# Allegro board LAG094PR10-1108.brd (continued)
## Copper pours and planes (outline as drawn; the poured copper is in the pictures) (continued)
LG_VNN on BOTTOM (solid shape): 85.8,131.33 85.8,130.46 85.85,130.41 85.85,128.94 85.77,128.86 85.44,128.86 85.37,128.94 85.37,129.92 85.57,130.12 85.57,130.44 85.59,130.46 85.59,131.33 85.64,131.38 85.75,131.38
LG_VNN on IN2 (solid shape): 84.64,123.55 84.64,122.98 84.77,122.86 84.77,122.41 84.64,122.28 83.85,122.28 83.7,122.44 83.7,122.79 83.88,122.97 83.88,123.58 84.62,123.58
LG_VNN on IN2 (solid shape): 85.82,129.82 85.82,128.36 85.44,127.98 84.99,127.98 84.74,128.23 84.74,128.68 84.93,128.87 84.93,129.82 85.05,129.95 85.69,129.95
LX_1.2V on TOP (solid shape): 24.23,115.92 24.23,115.16 23.85,114.78 23.82,114.8 23.4,114.74 23.34,114.32 23.36,114.29 23.28,114.21 23.28,114.17 23.21,114.1 23.21,113.71 23.21,113.71 23.21,113.41 23.15,113.34 22.56,113.34 22.46,113.44 22.46,114.98 22.48,114.99 22.6,115.08 22.66,115.21 22.67,115.23 22.91,115.46 23.54,115.46 23.58,115.5 23.6,115.5 24.08,115.97 24.18,115.97
LX_1.2V on BOTTOM (solid shape): 23.34,104.77 26.01,104.77 26.13,104.64 26.13,103.69 26.07,103.63 22.26,103.63 21.94,103.31 20.42,103.31 19.85,102.74 17.88,102.74 17.31,103.31 17.31,105.98 17.5,106.17 21.94,106.17
LX_1.2V on IN2 (solid shape): 23.66,104.9 23.66,103.82 23.47,103.63 23.08,103.63 22.83,103.88 22.83,104.96 22.89,105.02 23.53,105.02
LX_1.2V on IN2 (solid shape): 23.66,115.25 23.66,114.99 23.28,114.61 23.28,114.23 23.08,114.04 22.58,114.04 22.51,114.1 22.51,114.99 22.89,115.37 23.53,115.37
LX_1.05V on TOP (solid shape): 144.23,63.34 144.23,60.87 144.2,60.84 143.24,60.84 143.04,61.04 143.04,63.29 143.24,63.5 144.08,63.5
LX_1.05V on BOTTOM (solid shape): 149.2,63.81 149.2,61.91 149.07,61.78 147.84,61.78 147.4,62.21 145.96,62.21 145.5,61.76 145.5,60.08 145.27,59.85 142.9,59.85 142.87,59.86 142.82,59.87 142.77,59.88 142.72,59.87 142.67,59.86 142.64,59.85 142.27,59.85 142.23,59.86 142.18,59.87 142.13,59.88 142.08,59.87 142.03,59.86 141.99,59.85 141.94,59.9 141.94,62.92 142.3,63.28 144.25,63.28 144.25,63.23 144.26,63.18 144.27,63.13 144.29,63.08 144.32,63.03 144.36,63 144.4,62.96 144.45,62.94 144.5,62.92 144.55,62.9 144.6,62.9 144.66,62.9 144.71,62.92 144.76,62.94 144.8,62.96 144.85,63 144.88,63.03 144.91,63.08 144.94,63.13 144.95,63.18 144.96,63.23 144.96,63.28 144.95,63.34 144.94,63.39 144.91,63.44 144.88,63.48 144.85,63.52 144.8,63.55 144.76,63.58 144.71,63.6 144.66,63.61 144.6,63.61 144.55,63.61 144.5,63.6 144.45,63.58 144.4,63.55 144.36,63.52 144.32,63.48 144.29,63.44 144.27,63.39 144.26,63.34 144.25,63.28 142.3,63.28 143.02,64 149.01,64
LX_1.8V on TOP (solid shape): 51.66,34.16 51.66,33.08 51.22,32.63 49.31,32.63 49.18,32.76 49.18,33.65 49.31,33.78 49.37,33.78 49.88,34.29 51.53,34.29
LX_1.8V on BOTTOM (solid shape): 52.1,33.84 52.1,31.11 51.98,30.98 49.63,30.98 48.23,32.38 47.34,32.38 47.28,32.44 47.28,33.08 47.34,33.14 48.17,33.14 48.87,33.84 49.63,33.84 49.75,33.97 51.98,33.97
LX_1.24V on TOP (solid shape): 65.92,43.52 65.92,37.81 65.69,37.59 62.96,37.59 62.9,37.65 62.9,38.67 62.96,38.73 64.55,38.73 64.87,39.05 64.87,42.41 64.61,42.67 63.79,42.67 63.72,42.73 63.72,43.37 63.79,43.43 64.68,43.43 64.93,43.68 65.76,43.68
LX_1.24V on BOTTOM (solid shape): 67.03,43.24 67.03,37.78 66.01,36.76 63.41,36.76 63.22,36.95 63.22,39.37 64.68,40.83 64.68,43.24 64.93,43.49 66.77,43.49
LX_3V on TOP (solid shape): 165.4,60.57 165.48,60.53 165.5,60.44 165.83,59.96 166.17,60.44 166.18,60.53 166.26,60.57 170.21,60.57 170.4,60.38 170.4,59.62 170.28,59.5 166.54,59.5 165.64,59.49 165.26,59.11 163.48,59.11 163.36,59.24 163.36,60.45 163.48,60.57
LX_3V on BOTTOM (solid shape): 170.4,59.94 170.4,59.43 170.09,59.11 168.94,59.11 168.88,59.18 168.88,59.37 169.52,60 170.34,60
LX_3V on BOTTOM (solid shape): 164.75,61.65 164.88,61.53 164.88,61.08 165.07,60.89 166.09,60.89 166.53,60.45 166.53,59.49 166.72,59.3 166.72,58.73 166.66,58.67 165.77,58.67 165.64,58.8 165.5,58.8 165.02,58.8 165.02,58.8 164.5,58.8 164.37,58.67 159.55,58.67 159.42,58.8 159.42,60.35 165.48,60.35 165.48,60.29 165.48,60.24 165.5,60.19 165.52,60.14 165.55,60.1 165.59,60.06 165.63,60.03 165.68,60 165.73,59.98 165.78,59.97 165.83,59.96 165.89,59.97 165.94,59.98 165.99,60 166.03,60.03 166.08,60.06 166.11,60.1 166.14,60.14 166.16,60.19 166.18,60.24 166.19,60.29 166.19,60.35 166.18,60.4 166.16,60.45 166.14,60.5 166.11,60.54 166.08,60.58 166.03,60.62 165.99,60.64 165.94,60.66 165.89,60.67 165.83,60.68 165.78,60.67 165.73,60.66 165.68,60.64 165.63,60.62 165.59,60.58 165.55,60.54 165.52,60.5 165.5,60.45 165.48,60.4 165.48,60.35 159.42,60.35 159.42,61.34 159.74,61.65 164.19,61.65
LX_5V on TOP (solid shape): outline of 97 points within 202.98,77.08 210.28,78.48
LX_5V on BOTTOM (solid shape): 204.38,78.74 204.38,78.61 204.25,78.48 204.25,78.04 204.12,77.91 203.86,77.91 203.62,78.01 203.37,77.91 203.04,77.91 202.98,77.97 202.98,78.74 203.04,78.8 204.31,78.8
LX_5V on BOTTOM (solid shape): 212,81.02 212,76.64 211.68,76.32 207.43,76.32 207.36,76.39 207.36,77.21 206.92,77.66 206.92,77.81 206.96,77.81 207.27,78.19 206.9,78.52 206.88,78.52 206.85,78.54 206.66,78.54 206.6,78.61 206.6,79.18 206.66,79.24 207.43,79.24 207.55,79.12 208.89,79.12 209.2,79.43 209.2,80.96 209.39,81.15 211.87,81.15
LX_CHG on TOP (solid shape): 182.96,51.06 182.96,49.28 182.89,49.21 181.97,49.21 181.87,49.31 181.87,49.87 181.8,49.94 181.14,49.94 181.06,50.02 181.06,51.04 181.14,51.11 182.91,51.11
LX_CHG on BOTTOM (solid shape): 193.65,48.89 193.65,48.83 193.58,48.76 192.88,48.76 192.31,48.19 192.31,47.81 191.55,47.05 190.6,47.05 190.41,47.24 190.41,47.87 190.57,48.04 191.68,48.04 191.99,48.35 192.04,48.37 192.09,48.39 192.14,48.39 192.7,48.95 193.58,48.95
LX_CHG on BOTTOM (solid shape): 183.1,51.68 183.1,49.97 183.49,49.59 184.12,49.59 184.37,49.33 184.37,46.48 184.18,46.29 179.17,46.29 178.72,46.73 178.72,49.59 181.16,49.59 181.16,49.54 181.17,49.48 181.19,49.43 181.21,49.39 181.24,49.34 181.27,49.3 181.32,49.27 181.36,49.24 181.41,49.22 181.46,49.21 181.52,49.21 181.57,49.21 181.62,49.22 181.67,49.24 181.72,49.27 181.76,49.3 181.8,49.34 181.83,49.39 181.85,49.43 181.86,49.48 181.87,49.54 181.87,49.59 181.86,49.64 181.85,49.69 181.83,49.74 181.8,49.79 181.76,49.82 181.72,49.86 181.67,49.88 181.62,49.9 181.57,49.92 181.52,49.92 181.46,49.92 181.41,49.9 181.36,49.88 181.32,49.86 181.27,49.82 181.24,49.79 181.21,49.74 181.19,49.69 181.17,49.64 181.16,49.59 178.72,49.59 178.72,51.49 179.04,51.81 182.98,51.81
LX_CHG on IN2 (solid shape): 192.29,48.22 192.29,47.68 192.01,47.4 190.92,47.4 190.76,47.56 190.76,48.27 190.84,48.34 192.16,48.34
LX_CHG on IN2 (solid shape): 183.55,49.75 183.55,49.16 183.41,49.02 181.98,49.02 181.87,49.13 181.87,49.75 181.97,49.85 183.45,49.85
LX_VCCGI on TOP (solid shape): 93.38,118.65 93.38,116.87 93.28,116.77 93.04,116.77 92.79,116.87 92.55,116.77 90.43,116.77 90.36,116.85 90.36,118.63 90.51,118.78 93.25,118.78
LX_VCCGI on BOTTOM (solid shape): 97.57,135.64 97.57,134.76 97.6,134.73 97.6,134.25 97.95,133.89 97.95,132.19 97.9,132.14 97.39,132.14 97.34,132.19 97.34,135.64 97.39,135.69 97.52,135.69
LX_VCCGI on BOTTOM (solid shape): outline of 96 points within 91.28,111.25 102.21,122.11
LX_VCCGI on IN2 (solid shape): 97.63,117.85 97.63,116.68 97.38,116.42 96.62,116.42 96.6,116.44 96.38,116.44 96.24,116.58 96.24,117.66 96.55,117.98 97.51,117.98
LX_VCCGI on IN2 (solid shape): 98.52,133.86 98.52,132.01 98.08,131.57 97.82,131.57 97.44,131.95 97.44,133.92 97.57,134.05 98.33,134.05
LX_VNN on TOP (solid shape): 85.75,119.38 85.83,119.33 85.84,119.23 86.08,118.74 86.52,119.07 86.59,119.16 86.69,119.14 86.78,119.06 86.78,116.87 86.62,116.71 85.63,116.71 85.51,116.84 85.51,117.66 84.62,118.55 84.62,119.18 84.81,119.38
LX_VNN on BOTTOM (solid shape): 86.2,131.33 86.2,130.44 86.23,130.41 86.23,129.93 86.58,129.57 86.58,127.87 86.53,127.82 86.03,127.82 85.97,127.87 85.97,131.33 86.03,131.38 86.15,131.38
LX_VNN on BOTTOM (solid shape): 85.94,122.08 85.94,119.44 85.78,119.29 85.78,118.8 85.89,118.7 86.91,118.7 87.63,117.98 87.63,116.49 87.38,116.23 85.98,116.23 85.98,117.18 85.09,117.18 85.09,116.23 83.76,116.23 83.76,119.03 84.17,119.44 84.67,119.44 84.81,119.58 84.81,122.17 84.9,122.26 85.75,122.26
LX_VNN on IN2 (solid shape): 86.8,129.31 86.8,127.74 86.67,127.61 86.2,127.61 86.04,127.77 86.04,129.58 86.17,129.71 86.41,129.71
LX_VNN on IN2 (solid shape): 85.89,120.01 85.89,119.3 85.81,119.13 85.84,118.93 85.86,118.9 85.76,118.8 84.87,118.8 84.74,118.93 84.74,119.69 85.12,120.07 85.82,120.07
Net_23 on TOP (solid shape): 218.97,70.29 210.97,70.29 210.97,78.29 218.97,78.29
Net_24 on TOP (solid shape): 60.61,103.44 52.61,103.44 52.61,111.44 60.61,111.44
QPCN_CHG on BOTTOM (solid shape): 194.79,48.13 194.79,46.86 193.77,45.84 193.77,44.83 193.71,44.76 192.63,44.76 192.57,44.83 192.57,45.78 192.82,46.03 193.39,46.03 194.6,47.24 194.6,48.13 194.66,48.19 194.73,48.19
QPCP_CHG on BOTTOM (solid shape): 195.61,48.13 195.61,46.99 195.93,46.67 195.93,45.91 195.74,45.72 194.85,45.72 194.6,45.46 194.6,44.76 194.55,44.72 194.02,44.72 193.96,44.78 193.96,45.72 194.34,46.1 195.11,46.1 195.42,46.41 195.42,48.13 195.49,48.19 195.55,48.19
REGOUT on TOP (solid shape): 17.9,87.24 18.32,87.24 18.39,87.18 18.39,86.55 18.45,86.48 19.21,86.48 19.47,86.74 20.61,86.74 20.93,86.42 20.93,85.66 20.86,85.59 18.07,85.59 17.94,85.72 17.94,86.36 17.37,86.92 17.37,87.32 17.52,87.47 17.68,87.47
REGOUT on BOTTOM (solid shape): 21.56,87.82 21.56,87.18 21.43,87.05 20.74,87.05 19.27,85.59 18.07,85.59 17.88,85.78 17.88,87.31 18.54,87.97 21.4,87.97
RING2 on TOP (solid shape): 33.03,17.1 33.03,16.34 32.77,16.09 32.77,15.17 32.72,15.12 32.6,15.12 32.55,15.17 32.55,17.13 32.62,17.2 32.93,17.2
RING2 on TOP (solid shape): 21.31,15.36 21.94,15.36 22.01,15.3 22.01,14.54 21.88,14.41 20.16,14.41 20.04,14.54 20.04,15.24 20.16,15.36 20.74,15.36 20.87,15.5 21.17,15.5
RING2 on BOTTOM (solid shape): 22.45,14.92 21.88,14.35 20.93,14.35 20.74,14.54 20.74,15.3 20.93,15.49 21.69,15.49 21.94,15.74 22.45,15.74
RING2 on BOTTOM (solid shape): 33.12,18.22 33.12,16.25 32.99,16.12 32.67,16.12 32.55,16.25 32.55,17.2 32.36,17.39 32.23,17.39 32.23,18.41 32.93,18.41
RING2_R on TOP (solid shape): 23.75,17.74 23.75,16.83 23.28,16.35 23.28,14.79 23.08,14.6 22.32,14.6 22.32,17.14 21.88,17.58 21.18,17.58 20.93,17.84 20.93,18.98 21.12,19.17 22.32,19.17
RING2_R on IN1 (solid shape): 21.5,18.79 21.5,17.9 20.54,16.95 20.16,16.95 19.91,17.2 19.91,17.71 20.48,18.28 20.48,18.79 20.67,18.98 21.31,18.98
RING2_R on IN1 (solid shape): 5.72,8.26 5.72,7.63 5.67,7.58 5.75,7.58 5.75,6.99 5.57,6.82 4.2,6.82 3.97,7.04 3.97,8.26 4.1,8.39 5.6,8.39
RTC_PWR on TOP (solid shape): 112.68,59.24 112.68,58.86 112.43,58.61 112.43,56.57 112.37,56.51 111.86,56.51 111.6,56.76 111.29,56.76 110.97,56.45 109.55,56.45 109.33,56.67 109.33,57.33 109.68,57.69 110.16,57.69 111.12,58.65 111.12,59.43 111.25,59.56 112.37,59.56
SLEEVE on TOP (solid shape): 18.77,15.11 18.77,13.33 18.36,12.92 17.73,12.92 17.62,13.03 17.62,15.04 17.75,15.17 18.7,15.17
SLEEVE on IN1 (solid shape): 19.15,14.98 19.15,13.97 19.08,13.9 17.75,13.9 17.62,14.03 17.62,14.92 17.75,15.04 19.08,15.04
SLEEVE on IN1 (solid shape): 32.42,17.58 32.42,16.31 32.29,16.19 31.78,16.19 31.66,16.31 31.66,16.76 31.4,17.01 31.21,17.01 31.21,18.03 31.97,18.03
SLEEVE_R on TOP (solid shape): 20.61,18.98 20.61,17.78 19.91,17.08 19.91,14.73 19.78,14.6 19.08,14.6 18.96,14.73 18.96,18.98 19.15,19.17 20.42,19.17
SLEEVE_R on IN1 (solid shape): 5.57,18.07 5.57,17.08 5.39,16.9 3.36,16.9 3.26,17 3.26,18.07 3.34,18.14 5.27,18.14 5.29,18.17 5.47,18.17
SLEEVE_R on IN1 (solid shape): 19.66,18.85 19.66,17.9 18.64,16.89 18.26,16.89 17.94,17.2 17.94,17.65 18.7,18.41 18.7,18.79 18.89,18.98 19.53,18.98
SN_1.2V on TOP (solid shape): 22.96,102.8 22.96,102.17 22.89,102.1 20.93,102.1 20.74,102.29 20.74,103.94 20.8,104.01 21.75,104.01
SN_1.05V on TOP (solid shape): 147.99,62.54 147.99,61.34 147.86,61.21 147.23,61.21 146.91,60.89 145.89,60.89 145.83,60.96 145.83,62.61 145.89,62.67 147.86,62.67
SN_1.8V on TOP (solid shape): 51.79,31.3 52.55,31.3 52.55,30.73 52.36,30.54 49.88,30.54 49.88,31.55 51.53,31.55
SN_1.24V on TOP (solid shape): 64.61,41.33 64.61,39.87 64.3,39.56 62.01,39.56 61.95,39.62 61.95,40.13 62.01,40.19 62.77,40.19 62.96,40.38 62.96,41.33 63.03,41.4 64.55,41.4
SN_3V on TOP (solid shape): 166.66,57.53 166.66,56.7 166.59,56.64 165.45,56.64 165.26,56.45 163.42,56.45 163.36,56.51 163.36,57.59 163.42,57.65 166.53,57.65
SN_5V on TOP (solid shape): 210.22,81.08 210.22,80.01 210.09,79.88 207.55,79.88 207.49,79.94 207.49,80.7 207.55,80.77 208.06,80.77 208.44,81.15 210.16,81.15
SN_CHG on TOP (solid shape): 183.82,48.28 183.82,47.39 183.75,47.33 181.15,47.33 181.15,48.34 183.75,48.34
SN_VCCGI on TOP (solid shape): 92.12,121.54 92.12,119.52 92.02,119.43 90.45,119.43 90.37,119.5 90.37,120.75 91.3,121.67 91.98,121.67
SN_VNN on TOP (solid shape): 84.11,119.25 84.11,116.84 83.98,116.71 82.97,116.71 82.84,116.84 82.84,119.25 82.97,119.38 83.98,119.38
UG_1.2V on TOP (solid shape): 24.63,115.95 24.63,114.05 24.45,113.87 23.96,113.87 23.84,113.98 23.84,114.18 24,114.39 23.97,114.65 24.41,115.08 24.41,115.95 24.46,116 24.58,116
UG_1.2V on BOTTOM (solid shape): 24.16,106.61 24.16,105.85 24.04,105.72 23.47,105.72 23.34,105.6 23.08,105.6 22.96,105.72 22.96,106.61 23.08,106.74 24.04,106.74
UG_1.2V on IN2 (solid shape): 24.99,114.93 24.99,113.98 24.93,113.91 24.16,113.91 24.04,114.04 24.04,114.8 24.23,114.99 24.93,114.99
UG_1.2V on IN2 (solid shape): 24.55,107.88 24.55,105.91 24.23,105.6 23.08,105.6 22.96,105.72 22.96,106.61 23.85,107.5 23.85,107.82 24.04,108.01 24.42,108.01
UG_CHG on BOTTOM (solid shape): 193.66,49.31 193.66,49.21 193.61,49.16 192.72,49.16 192.08,48.52 191.75,48.52 191.7,48.57 191.7,48.85 192.21,49.36 193.61,49.36
UG_CHG on BOTTOM (solid shape): 183.1,52.7 183.1,52.13 182.98,52 180.88,52 180.76,52.13 180.76,52.76 180.82,52.83 182.98,52.83
UG_CHG on IN2 (solid shape): 182.51,52.56 182.51,52.15 182.2,51.85 180.88,51.85 180.81,51.93 180.81,52.48 180.93,52.61 182.46,52.61
UG_CHG on IN2 (solid shape): 192.22,49.82 192.29,49.8 192.37,49.81 192.54,49.64 192.54,48.8 192.21,48.47 191.5,48.47 191.35,48.62 191.35,49.69 191.47,49.82
UG_VCCGI on BOTTOM (solid shape): 97.98,135.64 97.98,134.73 98.36,134.35 98.71,134.35 98.79,134.27 98.79,133.31 98.76,133.28 98.13,133.28 98.13,133.97 97.75,134.35 97.75,135.64 97.8,135.69 97.93,135.69
UG_VCCGI_R on BOTTOM (solid shape): 98.71,118.8 98.71,118.54 98.71,117.66 98.55,117.5 97.67,117.5 97.51,117.66 97.51,118.8 97.7,118.99 98.52,118.99
UG_VCCGI_R on BOTTOM (solid shape): 100.19,134.2 100.19,133.28 100.11,133.21 99.04,133.21 98.97,133.28 98.97,134.15 99.07,134.25 100.14,134.25
UG_VCCGI_R on IN2 (solid shape): 99.94,134.11 99.94,132.48 99.86,132.39 98.93,132.39 98.93,134.11 99.12,134.3 99.75,134.3
UG_VCCGI_R on IN2 (solid shape): 99.41,119.5 99.41,118.99 98.9,118.49 98.9,117.91 98.78,117.79 98.08,117.79 97.95,117.91 97.95,118.93 98.71,119.69 99.22,119.69
UG_VNN on BOTTOM (solid shape): 88.55,122.8 88.55,121.92 88.36,121.72 86.97,121.72 86.84,121.85 86.84,122.8 86.97,122.93 88.43,122.93
UG_VNN on BOTTOM (solid shape): 86.61,131.33 86.61,130.45 87.03,130.03 87.27,130.03 87.58,129.73 87.58,129.23 87.47,129.13 87.14,129.13 86.76,129.51 86.76,129.65 86.38,130.03 86.38,131.33 86.43,131.38 86.56,131.38
UG_VNN on IN2 (solid shape): 87.77,129.43 87.77,128.47 87.18,128.47 87.01,128.65 87.01,129.43 86.69,129.74 86.69,129.94 86.82,130.06 87.14,130.06
UG_VNN on IN2 (solid shape): 88.24,123.38 88.32,123.25 88.45,123.18 88.49,123.17 88.49,122.42 88.3,122.23 87.47,122.23 87.35,122.36 87.35,123.19 87.57,123.41 88.22,123.41
USB20_VCC on BOTTOM (solid shape): 201.52,38.73 201.52,36.32 201.33,36.13 196.56,36.13 196.38,36.31 196.38,38.73 196.69,39.05 201.2,39.05
USB30_VCCA on TOP (solid shape): outline of 149 points within 14.64,32 20.04,57.46
USB30_VCCA on BOTTOM (solid shape): 17.18,42.39 17.18,39.05 16.86,38.73 15.48,38.73 15.37,38.84 15.37,42.38 15.59,42.59 16.97,42.59
USB30_VCCA on BOTTOM (solid shape): 19.53,57.72 19.53,53.72 19.47,53.65 18,53.65 17.94,53.72 17.94,55.37 17.18,56.13 15.86,56.13 15.4,56.59 15.4,57.53 15.85,57.97 19.27,57.97
VNN_N15 on BOTTOM (solid shape): 85.01,131.38 85.01,130.46 84.58,130.03 84.58,128.8 84.01,128.23 84.01,128 83.85,127.85 82.51,127.85 82.46,127.9 82.46,128.68 82.48,128.71 83.4,128.71 83.6,128.91 83.6,130.07 83.92,130.39 84.58,130.39 84.78,130.59 84.78,131.38 84.83,131.43 84.96,131.43
VNN_N16 on BOTTOM (solid shape): 82.2,131.61 82.2,130.08 82.1,129.98 81.26,129.98 81.21,130.03 81.21,131.68 82.13,131.68
N17415515 on BOTTOM (solid shape): 78.6,147.02 78.95,146.71 79.31,147.02 79.31,147.06 80.64,147.06 80.88,146.97 81.12,147.06 83.74,147.06 84.05,146.75 84.05,146.17 83.94,145.92 84.05,145.67 84.05,143.38 83.85,143.19 76.78,143.19 76.33,143.64 76.33,144.73 76.31,144.76 75.8,144.76 75.79,144.76 75.79,145.01 75.79,145.01 76.34,145.01 76.34,145.02 76.34,145.56 76.34,145.56 75.79,145.56 75.79,145.56 75.79,145.81 75.79,145.82 76.33,145.82 76.34,145.82 76.34,145.91 76.36,145.91 76.36,146.87 76.55,147.06 78.59,147.06
N21380741 on BOTTOM (solid shape): 208.06,81.34 208.06,80.01 207.93,79.88 207.44,79.88 207.44,79.88 206.6,79.88 206.54,79.94 206.54,80.58 206.6,80.64 207.43,80.64 207.55,80.77 207.55,81.28 207.68,81.4 208,81.4
N23133643 on BOTTOM (solid shape): 189.35,56.74 189.35,53.8 189.21,53.65 188.12,53.65 188,53.78 188,55.78 188.25,56.03 188.25,56.88 188.43,57.06 189.04,57.06
N29179188 on TOP (solid shape): 175.99,68.83 177.96,68.83 177.97,68.84 180.18,68.84 180.3,68.72 180.3,67.42 180.25,67.37 175.47,67.37 175.27,67.17 175.27,63.89 175.13,63.75 173.14,63.75 172.06,62.67 165.44,62.67 165.21,62.9 165.21,66.07 165.36,66.23 166.59,66.23 169.45,69.08 175.74,69.08
N29179461 on TOP (solid shape): 180.95,67.05 180.95,65.02 180.56,64.64 180.56,62.35 180.31,62.1 178.67,62.1 178.49,61.92 178.49,61.43 178.44,61.37 177.87,61.37 177.71,61.21 177.66,61.21 177.58,61.13 177.58,60.69 177.76,60.51 178.47,60.51 178.47,60 178.34,59.88 174.91,59.88 174.79,60 174.79,62.23 175.42,62.86 175.42,67.05 175.55,67.18 180.82,67.18
N29179461 on BOTTOM (solid shape): 179.76,67.05 179.76,65.35 179.56,65.15 175.36,65.15 175.29,65.21 175.29,67.05 175.42,67.18 179.64,67.18
N29179506 on TOP (solid shape): 166.59,68.77 166.59,66.92 166.47,66.8 165.39,66.8 165.26,66.92 165.26,67.37 165.9,68 165.9,68.77 165.96,68.83 166.53,68.83
N39399976 on TOP (solid shape): 206.82,58.03 206.82,56.99 206.66,56.83 204.89,56.83 204.73,56.99 204.73,58.03 204.79,58.1 206.76,58.1
N39399976 on BOTTOM (solid shape): 207.04,58.85 207.25,58.84 207.45,58.83 207.65,58.84 207.86,58.85 207.96,58.86 208.82,58.86 208.95,58.73 208.95,55.43 208.76,55.24 205.08,55.24 204.89,55.43 204.89,55.62 205.82,55.62 205.83,55.56 205.84,55.51 205.87,55.46 205.89,55.41 205.93,55.37 205.97,55.33 206.02,55.3 206.07,55.28 206.12,55.26 206.18,55.25 206.23,55.25 206.29,55.26 206.34,55.28 206.39,55.3 206.44,55.33 206.48,55.37 206.52,55.41 206.55,55.46 206.57,55.51 206.58,55.56 206.59,55.62 206.59,55.68 206.58,55.73 206.56,55.78 206.53,55.83 206.5,55.88 206.46,55.92 206.42,55.95 206.37,55.98 206.32,56 206.26,56.01 206.21,56.02 206.15,56.01 206.1,56 206.04,55.98 205.99,55.95 205.95,55.92 205.91,55.88 205.88,55.83 205.85,55.78 205.84,55.73 205.83,55.68 205.82,55.62 204.89,55.62 204.89,58.67 205.08,58.86 206.94,58.86
N40775614 on BOTTOM (solid shape): 107.18,41.5 107.18,40.9 107.15,40.89 106.9,40.55 107.15,40.21 107.18,40.2 107.18,39.88 106.63,39.32 105.77,39.32 105.77,39.32 105.27,39.32 105.17,39.42 105.17,40.11 105.2,40.15 105.22,40.15 105.49,40.3 105.54,40.61 105.54,40.61 105.54,41.34 105.59,41.39 106.12,41.39 106.27,41.55 107.14,41.55
N40775624 on BOTTOM (solid shape): 102.86,41.42 103.35,41.42 103.52,41.26 103.52,40.43 103.82,40.12 103.82,39.4 103.75,39.33 102.13,39.33 101.68,39.78 101.68,41.56 101.73,41.61 102.68,41.61

Small or netless copper shapes (teardrops, artwork), in the pictures only: 220 on TOP, 27 on BOTTOM, 7 on VCC, 7 on IN1, 7 on IN2, 7 on GND

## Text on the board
Ref Des/Silkscreen Bottom: SPK | KB | BL | DCIN | TP | BATTERY | HDD | ODD | IO | FP | POWER | EDP | M2L4 | DIMM A | SODIMM-ONLY SUPPORT DDR4
User.Comments: LA-G094P | 2018-11-06 | 2019-11-06 | Voilin | EDI55
Ref Des/Silkscreen Top: VGA
User.42: trace Width | Width/space | 5.9mil | 7.6mil | 4mil | 5mil | 4.5 / 5.2 | 5 / 5.4 | 4 / 4 | 3.5 / 7.6 | L2/L5 | L2 | L5 | SB_1_0mm-6L(4mil & 5mil 50ohm)_180125 | L1-TOP | L2-VCC | L3-IN1 | L4-IN2 | L5-GND | L6-BOT | LAYER | NAME | STACKUP: 6 LAYER | 42 ohm | 50 ohm | THICKNESS=1.0mm | 85 ohm | 100 ohm | Ref
User.43: FIGURE | SIZE | 8.0 | 22.0 | 28.0 | 35.0 | 118.0 | 126.0 | 130.0 | 154.0 | 43.0 | 63.0 | 220.0 | 55.0x24.0 | 63.0x24.0 | 63.0x35.0 | 71.0x31.0 | 102.0x31.0 | 157.0x118.0 | DRILL CHART: TOP to BOTTOM | ALL UNITS ARE IN MILS | TOLERANCE | +3.0/-3.0 | +2.0/-2.0 | PLATED | NON-PLATED | QTY | 3545 | 19 | 18 | 8 | 6 | 1 | 4 | 3 | 7
User.45: STACK-UP SETTING OK
